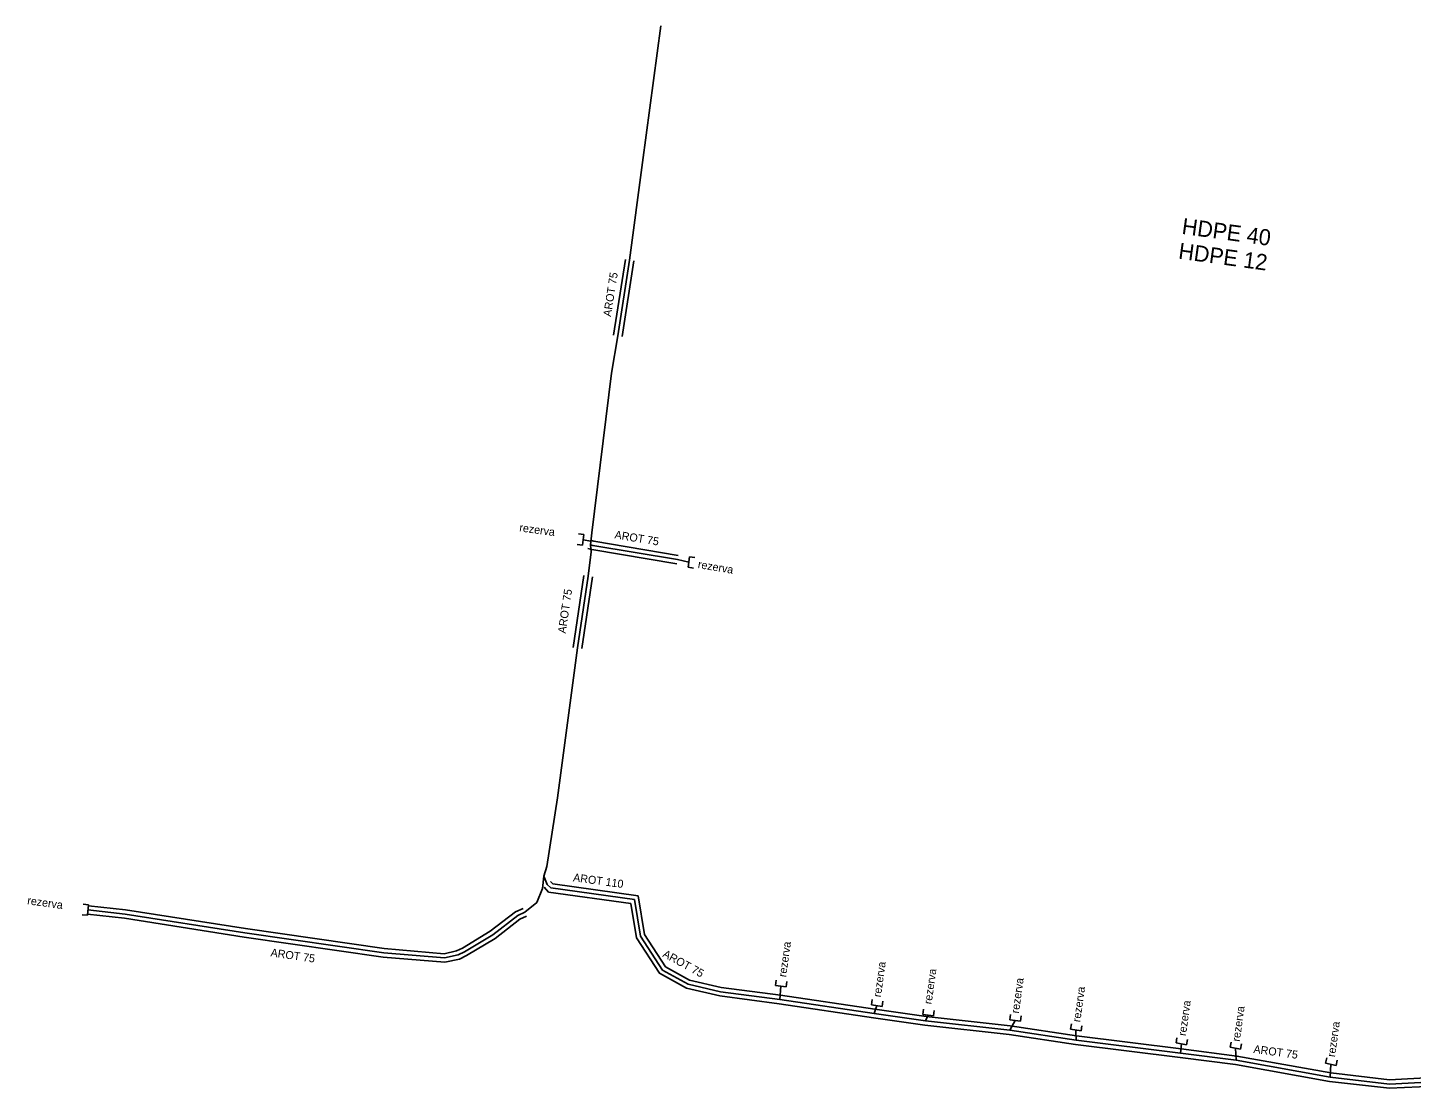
# Model space of a CAD drawing. Extents: x -651943 to -618711, y -1138561 to -1100552.
# Drawn here: x -632123.2 to -631993.6, y -1114988.6 to -1114889.2 of the extents above; entities that cross this region are included whole.
import ezdxf

# ---------------------------------------------------------------- set-up
doc = ezdxf.new("R2010")
doc.units = 0
for name, color, linetype in [('KT optika', 7, 'Continuous'), ('KT trasa', 7, 'Continuous'), ('KT zařízení', 7, 'Continuous')]:
    doc.layers.add(name, color=color, linetype=linetype)

# ---------------------------------------------------------------- blocks, each defined once
blk = doc.blocks.new('TVREZ')
at = {"layer": 'KT zařízení'}
for p, q in [((-0.05, 0.05), (0, 0.05)), ((0, -0.05), (0, 0.05)), ((-0.05, -0.05), (0, -0.05))]:
    blk.add_line(p, q, dxfattribs=at)

msp = doc.modelspace()

# ---------------------------------------------------------------- linework, layer by layer
at = {"layer": 'KT optika'}
for p, q in [((-632065.6, -1114901.82), (-632063.88, -1114889)), ((-632066.81, -1114910.97), (-632065.6, -1114901.82)), ((-632067.92, -1114918.06), (-632066.81, -1114910.97)), ((-632068.51, -1114921.57), (-632067.92, -1114918.06)), ((-632070.36, -1114936.54), (-632068.51, -1114921.57)), ((-632071.17, -1114937.19), (-632070.44, -1114937.31)), ((-632070.47, -1114937.66), (-632070.36, -1114936.54)), ((-632070.7, -1114940.61), (-632070.42, -1114938.32)), ((-632070.42, -1114938.32), (-632070.47, -1114937.66)), ((-632070.27, -1114937.72), (-632070.47, -1114937.66)), ((-632062.32, -1114939.04), (-632070.27, -1114937.72)), ((-632061.26, -1114939.27), (-632062.32, -1114939.04)), ((-632071.7, -1114947.33), (-632070.7, -1114940.61)), ((-632073.56, -1114961.37), (-632071.7, -1114947.33)), ((-632074.56, -1114967.82), (-632073.56, -1114961.37)), ((-632074.84, -1114968.72), (-632074.56, -1114967.82)), ((-632075.52, -1114971.2), (-632074.97, -1114969.88)), ((-632074.97, -1114969.88), (-632074.84, -1114968.72)), ((-632074.84, -1114968.72), (-632074.53, -1114969.49)), ((-632074.53, -1114969.49), (-632074.21, -1114969.83)), ((-632074.21, -1114969.83), (-632066.36, -1114970.91)), ((-632076.63, -1114972.11), (-632075.52, -1114971.2)), ((-632066.36, -1114970.91), (-632065.8, -1114974.34)), ((-632114.09, -1114972.27), (-632117.57, -1114971.89)), ((-632102.86, -1114974.03), (-632114.09, -1114972.27)), ((-632077.3, -1114972.4), (-632079.64, -1114974.22)), ((-632076.63, -1114972.11), (-632077.3, -1114972.4)), ((-632089.86, -1114975.91), (-632102.86, -1114974.03)), ((-632079.64, -1114974.22), (-632082.29, -1114975.81)), ((-632065.8, -1114974.34), (-632063.74, -1114977.52)), ((-632084.17, -1114976.39), (-632089.86, -1114975.91)), ((-632082.88, -1114976.11), (-632084.17, -1114976.39)), ((-632082.29, -1114975.81), (-632082.88, -1114976.11)), ((-632063.74, -1114977.52), (-632061.33, -1114978.84)), ((-632061.33, -1114978.84), (-632058.29, -1114979.56)), ((-632052.74, -1114980.29), (-632052.64, -1114979.04)), ((-632058.29, -1114979.56), (-632052.74, -1114980.29)), ((-632052.74, -1114980.29), (-632043.89, -1114981.59)), ((-632043.66, -1114980.86), (-632043.89, -1114981.59)), ((-632043.89, -1114981.59), (-632039.09, -1114982.28)), ((-632038.85, -1114981.75), (-632039.09, -1114982.28)), ((-632039.09, -1114982.28), (-632031.2, -1114983.15)), ((-632031.2, -1114983.15), (-632030.68, -1114982.24)), ((-632031.2, -1114983.15), (-632024.98, -1114984.09)), ((-632025.01, -1114983.15), (-632024.98, -1114984.09)), ((-632024.98, -1114984.09), (-632015.18, -1114985.31)), ((-632015.18, -1114985.31), (-632015.11, -1114984.44)), ((-632015.18, -1114985.31), (-632009.97, -1114985.98)), ((-632009.97, -1114985.98), (-632010.05, -1114984.85)), ((-632009.97, -1114985.98), (-632001.18, -1114987.56)), ((-632001.11, -1114986.35), (-632001.18, -1114987.56)), ((-632001.18, -1114987.56), (-631995.61, -1114988.21)), ((-631995.61, -1114988.21), (-631991.52, -1114988))]:
    msp.add_line(p, q, dxfattribs=at)
at = {"layer": 'KT trasa'}
for p, q in [((-632065.6, -1114901.82), (-632063.88, -1114889)), ((-632066.81, -1114910.97), (-632065.6, -1114901.82)), ((-632067.92, -1114918.06), (-632066.81, -1114910.97)), ((-632068.51, -1114921.57), (-632067.92, -1114918.06)), ((-632070.36, -1114936.54), (-632068.51, -1114921.57)), ((-632071.17, -1114937.19), (-632070.44, -1114937.31)), ((-632070.47, -1114937.66), (-632070.36, -1114936.54)), ((-632070.7, -1114940.61), (-632070.42, -1114938.32)), ((-632070.42, -1114938.32), (-632070.47, -1114937.66)), ((-632070.27, -1114937.72), (-632070.47, -1114937.66)), ((-632062.32, -1114939.04), (-632070.27, -1114937.72)), ((-632061.26, -1114939.27), (-632062.32, -1114939.04)), ((-632071.7, -1114947.33), (-632070.7, -1114940.61)), ((-632073.56, -1114961.37), (-632071.7, -1114947.33)), ((-632074.56, -1114967.82), (-632073.56, -1114961.37)), ((-632074.84, -1114968.72), (-632074.56, -1114967.82)), ((-632075.52, -1114971.2), (-632074.97, -1114969.88)), ((-632074.97, -1114969.88), (-632074.84, -1114968.72)), ((-632074.84, -1114968.72), (-632074.53, -1114969.49)), ((-632074.53, -1114969.49), (-632074.21, -1114969.83)), ((-632074.21, -1114969.83), (-632066.36, -1114970.91)), ((-632076.63, -1114972.11), (-632075.52, -1114971.2)), ((-632066.36, -1114970.91), (-632065.8, -1114974.34)), ((-632114.09, -1114972.27), (-632117.57, -1114971.89)), ((-632102.86, -1114974.03), (-632114.09, -1114972.27)), ((-632077.3, -1114972.4), (-632079.64, -1114974.22)), ((-632076.63, -1114972.11), (-632077.3, -1114972.4)), ((-632089.86, -1114975.91), (-632102.86, -1114974.03)), ((-632079.64, -1114974.22), (-632082.29, -1114975.81)), ((-632065.8, -1114974.34), (-632063.74, -1114977.52)), ((-632084.17, -1114976.39), (-632089.86, -1114975.91)), ((-632082.88, -1114976.11), (-632084.17, -1114976.39)), ((-632082.29, -1114975.81), (-632082.88, -1114976.11)), ((-632063.74, -1114977.52), (-632061.33, -1114978.84)), ((-632061.33, -1114978.84), (-632058.29, -1114979.56)), ((-632052.74, -1114980.29), (-632052.64, -1114979.04)), ((-632058.29, -1114979.56), (-632052.74, -1114980.29)), ((-632052.74, -1114980.29), (-632043.89, -1114981.59)), ((-632043.66, -1114980.86), (-632043.89, -1114981.59)), ((-632043.89, -1114981.59), (-632039.09, -1114982.28)), ((-632038.85, -1114981.75), (-632039.09, -1114982.28)), ((-632039.09, -1114982.28), (-632031.2, -1114983.15)), ((-632031.2, -1114983.15), (-632030.68, -1114982.24)), ((-632031.2, -1114983.15), (-632024.98, -1114984.09)), ((-632025.01, -1114983.15), (-632024.98, -1114984.09)), ((-632024.98, -1114984.09), (-632015.18, -1114985.31)), ((-632015.18, -1114985.31), (-632015.11, -1114984.44)), ((-632015.18, -1114985.31), (-632009.97, -1114985.98)), ((-632009.97, -1114985.98), (-632010.05, -1114984.85)), ((-632009.97, -1114985.98), (-632001.18, -1114987.56)), ((-632001.11, -1114986.35), (-632001.18, -1114987.56)), ((-632001.18, -1114987.56), (-631995.61, -1114988.21)), ((-631995.61, -1114988.21), (-631991.52, -1114988))]:
    msp.add_line(p, q, dxfattribs=at)
at = {"layer": 'KT zařízení'}
for p, q in [((-632068.32, -1114918), (-632067.21, -1114910.91)), ((-632067.52, -1114918.12), (-632066.41, -1114911.03)), ((-632067.52, -1114918.12), (-632066.41, -1114911.03)), ((-632070.18, -1114937.33), (-632070.52, -1114937.23)), ((-632062.25, -1114938.65), (-632070.18, -1114937.33)), ((-632070.36, -1114938.11), (-632070.74, -1114938.01)), ((-632062.39, -1114939.43), (-632070.36, -1114938.11)), ((-632072.1, -1114947.27), (-632071.1, -1114940.55)), ((-632071.3, -1114947.39), (-632070.3, -1114940.67)), ((-632074.82, -1114969.76), (-632074.4, -1114970.21)), ((-632074.24, -1114969.22), (-632074.02, -1114969.45)), ((-632074.02, -1114969.45), (-632066.02, -1114970.56)), ((-632074.4, -1114970.21), (-632066.71, -1114971.27))]:
    msp.add_line(p, q, dxfattribs=at)
for points in [[(-632066.71, -1114971.27), (-632066.18, -1114974.49), (-632064.02, -1114977.82), (-632061.47, -1114979.22), (-632058.36, -1114979.95), (-632052.79, -1114980.69)], [(-632066.02, -1114970.56), (-632065.42, -1114974.19), (-632063.46, -1114977.21), (-632061.19, -1114978.46), (-632058.22, -1114979.17), (-632052.69, -1114979.89)], [(-632117.61, -1114972.29), (-632114.14, -1114972.67), (-632102.92, -1114974.43), (-632089.91, -1114976.31), (-632084.14, -1114976.79), (-632082.74, -1114976.49), (-632082.1, -1114976.16), (-632079.41, -1114974.55), (-632077.1, -1114972.75), (-632076.47, -1114972.48)], [(-632117.53, -1114971.49), (-632114.04, -1114971.87), (-632102.8, -1114973.63), (-632089.82, -1114975.51), (-632084.2, -1114975.99), (-632083.02, -1114975.73), (-632082.48, -1114975.46), (-632079.87, -1114973.89), (-632077.51, -1114972.05), (-632076.79, -1114971.74)], [(-632052.68, -1114979.89), (-632043.83, -1114981.19), (-632039.04, -1114981.88), (-632031.15, -1114982.75), (-632024.93, -1114983.69), (-632015.13, -1114984.91), (-632009.91, -1114985.58), (-632001.12, -1114987.16), (-631995.6, -1114987.81), (-631991.64, -1114987.6), (-631990.51, -1114986.95), (-631989.53, -1114985.94), (-631988.93, -1114985.51), (-631988.23, -1114985.33), (-631987.35, -1114985.56)], [(-632052.8, -1114980.69), (-632043.95, -1114981.99), (-632039.14, -1114982.68), (-632031.25, -1114983.55), (-632025.04, -1114984.49), (-632015.23, -1114985.71), (-632010.03, -1114986.38), (-632001.24, -1114987.96), (-631995.62, -1114988.61), (-631991.4, -1114988.4), (-631990.01, -1114987.59), (-631989.01, -1114986.55), (-631988.59, -1114986.25), (-631988.23, -1114986.15), (-631987.57, -1114986.34)]]:
    msp.add_lwpolyline(points, dxfattribs=at)

# ---------------------------------------------------------------- block references
for p, xscale, yscale, rotation in [((-632071.17, -1114937.19), 10.000015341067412, 10.00001534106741, -8.130102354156), ((-632061.26, -1114939.27), 10.000018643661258, 10.000018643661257, 172.21473078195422), ((-632117.57, -1114971.89), 10.000020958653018, 10.000020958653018, -6.284358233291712), ((-632052.64, -1114979.04), 10.000002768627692, 10.000002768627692, -97.03354713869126), ((-632043.66, -1114980.86), 9.999998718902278, 9.999998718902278, -97.7982107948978), ((-632038.85, -1114981.75), 9.999995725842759, 9.99999572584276, -97.21181949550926), ((-632030.68, -1114982.24), 9.999998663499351, 9.999998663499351, -96.78495010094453), ((-632025.01, -1114983.15), 10.000006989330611, 10.000006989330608, -99.46438374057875), ((-632015.11, -1114984.44), 10.000022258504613, 10.00002225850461, -99.27481042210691), ((-632010.05, -1114984.85), 10.000006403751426, 10.000006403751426, -99.66189651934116), ((-632001.11, -1114986.35), 10.000011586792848, 10.000011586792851, -102.09393716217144)]:
    msp.add_blockref('TVREZ', p, dxfattribs=dict(at, xscale=xscale, yscale=yscale, rotation=rotation))

# ---------------------------------------------------------------- texts
for s, height, rotation, p in [('HDPE 40', 1.5, 352.1981, (-632015.13, -1114908.5)), ('HDPE 12', 1.5, 352.1981, (-632015.45, -1114910.82)), ('AROT 75', 0.75, 81.1021, (-632068.56, -1114916.31)), ('rezerva', 0.75, 352.2014, (-632077.18, -1114936.39)), ('AROT 75', 0.75, 350.5729, (-632068.26, -1114937.05)), ('rezerva', 0.75, 350.5727, (-632060.46, -1114939.83)), ('AROT 75', 0.75, 81.536, (-632072.81, -1114946)), ('AROT 110', 0.75, 352.1334, (-632072.14, -1114969.19)), ('rezerva', 0.75, 352.2236, (-632123.29, -1114971.35)), ('rezerva', 0.75, 82.1086, (-632052.15, -1114978.22)), ('AROT 75', 0.75, 351.7712, (-632100.49, -1114976.23)), ('AROT 75', 0.75, 331.224, (-632063.78, -1114976.23)), ('rezerva', 0.75, 82.1086, (-632043.27, -1114980.1)), ('rezerva', 0.75, 82.1086, (-632038.52, -1114980.76)), ('rezerva', 0.75, 82.1086, (-632030.34, -1114981.62)), ('rezerva', 0.75, 82.1086, (-632024.59, -1114982.44)), ('rezerva', 0.75, 82.1086, (-632014.69, -1114983.73)), ('rezerva', 0.75, 82.1086, (-632009.64, -1114984.26)), ('rezerva', 0.75, 82.1086, (-632000.72, -1114985.71)), ('AROT 75', 0.75, 352.1721, (-632008.39, -1114985.28))]:
    msp.add_text(s, height=height, rotation=rotation, dxfattribs=at).set_placement(p)

doc.saveas('drawing.dxf')
